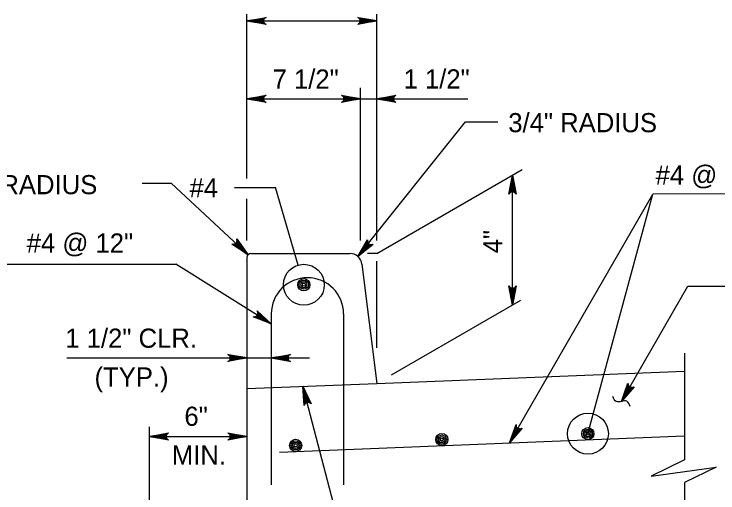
# Model space of a CAD drawing. Extents: x 2084213 to 2099800, y 976677 to 981262.
# Drawn here: x 2084499.7 to 2084861, y 980102.2 to 980348 of the extents above; entities that cross this region are included whole.
import ezdxf

# ---------------------------------------------------------------- set-up
doc = ezdxf.new("R2010")
doc.units = 0
doc.layers.add('1', color=7, linetype='Continuous')

msp = doc.modelspace()

# ---------------------------------------------------------------- linework, layer by layer
at = {"layer": '1'}
for p, q in [((2084619.23, 980263.61), (2084619.23, 980348)), ((2084685.9, 980231.81), (2084685.9, 980348)), ((2084619.23, 980344.49), (2084685.9, 980344.49)), ((2084677.57, 980231.81), (2084677.57, 980310.17)), ((2084619.23, 980304.49), (2084732.61, 980304.49)), ((2084676.18, 980223.52), (2084731.38, 980292.64)), ((2084731.38, 980292.64), (2084748.01, 980292.64)), ((2084685.9, 980225.09), (2084760.44, 980268.13)), ((2084755.54, 980198.63), (2084755.54, 980265.3)), ((2084565.45, 980261.28), (2084580.38, 980261.28)), ((2084619.84, 980224.48), (2084580.38, 980261.28)), ((2084612.8, 980258.99), (2084633.86, 980258.99)), ((2084645.5, 980219.13), (2084633.86, 980258.99)), ((2084619.23, 980231.81), (2084619.23, 980253.12)), ((2084754.04, 980127.85), (2084827.52, 980255.57)), ((2084794.23, 980132.58), (2084827.52, 980255.57)), ((2084899.18, 980255.69), (2084827.52, 980255.57)), ((2084621.31, 980225.09), (2084672.05, 980225.09)), ((2084685.9, 980225.09), (2084681.03, 980225.09)), ((2084619.23, 980223.01), (2084619.23, 980089.1)), ((2084685.9, 980176.64), (2084685.9, 980221.15)), ((2084493.44, 980219.64), (2084582.81, 980219.64)), ((2084631.73, 980188.93), (2084582.81, 980219.64)), ((2084678.25, 980219.61), (2084685.9, 980158.42)), ((2084648.44, 980209.05), (2084648.44, 980209.05)), ((2084811.49, 980149.12), (2084845.5, 980208.25)), ((2084845.5, 980208.25), (2084884.47, 980208.25)), ((2084693.43, 980162.77), (2084759.85, 980201.12)), ((2084631.73, 980194.09), (2084631.73, 980106.27)), ((2084668.84, 980194.08), (2084668.84, 980106.26)), ((2084843.77, 980173.96), (2084843.77, 980119.13)), ((2084526.78, 980171.44), (2084651.34, 980171.44)), ((2084685.9, 980158.42), (2084843.77, 980164.73)), ((2084619.23, 980155.75), (2084685.9, 980158.42)), ((2084684.41, 980017.39), (2084647.99, 980156.9)), ((2084569.27, 980092.34), (2084569.27, 980136.03)), ((2084569.27, 980131.17), (2084619.23, 980131.17)), ((2084635.9, 980123.12), (2084843.77, 980131.44)), ((2084794.23, 980132.58), (2084794.23, 980132.58)), ((2084843.77, 980107.59), (2084843.77, 980038.92))]:
    msp.add_line(p, q, dxfattribs=at)
for points in [[(2084619.23, 980344.49), (2084629.01, 980346.33), (2084628.63, 980346.07), (2084628.26, 980345.81), (2084628.06, 980345.48), (2084627.87, 980345.15), (2084627.81, 980344.82), (2084627.76, 980344.49), (2084627.81, 980344.17), (2084627.87, 980343.84), (2084628.06, 980343.51), (2084628.26, 980343.18), (2084628.63, 980342.92), (2084629.01, 980342.66), (2084619.23, 980344.49), (2084628.63, 980342.92), (2084628.26, 980343.18), (2084619.23, 980344.49), (2084628.06, 980343.51), (2084627.87, 980343.84), (2084619.23, 980344.49), (2084627.81, 980344.17), (2084627.76, 980344.49), (2084619.23, 980344.49), (2084627.81, 980344.82), (2084627.87, 980345.15), (2084619.23, 980344.49), (2084628.06, 980345.48), (2084628.26, 980345.81), (2084619.23, 980344.49), (2084628.63, 980346.07)], [(2084685.9, 980344.49), (2084676.11, 980342.66), (2084676.49, 980342.92), (2084676.86, 980343.18), (2084677.06, 980343.51), (2084677.25, 980343.84), (2084677.31, 980344.17), (2084677.37, 980344.49), (2084677.31, 980344.82), (2084677.25, 980345.15), (2084677.06, 980345.48), (2084676.86, 980345.81), (2084676.49, 980346.07), (2084676.11, 980346.33), (2084685.9, 980344.49), (2084676.49, 980346.07), (2084676.86, 980345.81), (2084685.9, 980344.49), (2084677.06, 980345.48), (2084677.25, 980345.15), (2084685.9, 980344.49), (2084677.31, 980344.82), (2084677.37, 980344.49), (2084685.9, 980344.49), (2084677.31, 980344.17), (2084677.25, 980343.84), (2084685.9, 980344.49), (2084677.06, 980343.51), (2084676.86, 980343.18), (2084685.9, 980344.49), (2084676.49, 980342.92)], [(2084619.23, 980304.49), (2084629.01, 980306.33), (2084628.63, 980306.07), (2084628.26, 980305.81), (2084628.06, 980305.48), (2084627.87, 980305.15), (2084627.81, 980304.82), (2084627.76, 980304.49), (2084627.81, 980304.17), (2084627.87, 980303.84), (2084628.06, 980303.51), (2084628.26, 980303.18), (2084628.63, 980302.92), (2084629.01, 980302.66), (2084619.23, 980304.49), (2084628.63, 980302.92), (2084628.26, 980303.18), (2084619.23, 980304.49), (2084628.06, 980303.51), (2084627.87, 980303.84), (2084619.23, 980304.49), (2084627.81, 980304.17), (2084627.76, 980304.49), (2084619.23, 980304.49), (2084627.81, 980304.82), (2084627.87, 980305.15), (2084619.23, 980304.49), (2084628.06, 980305.48), (2084628.26, 980305.81), (2084619.23, 980304.49), (2084628.63, 980306.07)], [(2084677.57, 980304.49), (2084667.78, 980302.66), (2084668.16, 980302.92), (2084668.53, 980303.18), (2084668.73, 980303.51), (2084668.92, 980303.84), (2084668.98, 980304.17), (2084669.04, 980304.49), (2084668.98, 980304.82), (2084668.92, 980305.15), (2084668.73, 980305.48), (2084668.53, 980305.81), (2084668.16, 980306.07), (2084667.78, 980306.33), (2084677.57, 980304.49), (2084668.16, 980306.07), (2084668.53, 980305.81), (2084677.57, 980304.49), (2084668.73, 980305.48), (2084668.92, 980305.15), (2084677.57, 980304.49), (2084668.98, 980304.82), (2084669.04, 980304.49), (2084677.57, 980304.49), (2084668.98, 980304.17), (2084668.92, 980303.84), (2084677.57, 980304.49), (2084668.73, 980303.51), (2084668.53, 980303.18), (2084677.57, 980304.49), (2084668.16, 980302.92)], [(2084685.9, 980304.49), (2084695.68, 980306.33), (2084695.3, 980306.07), (2084694.93, 980305.81), (2084694.73, 980305.48), (2084694.54, 980305.15), (2084694.48, 980304.82), (2084694.43, 980304.49), (2084694.48, 980304.17), (2084694.54, 980303.84), (2084694.73, 980303.51), (2084694.93, 980303.18), (2084695.3, 980302.92), (2084695.68, 980302.66), (2084685.9, 980304.49), (2084695.3, 980302.92), (2084694.93, 980303.18), (2084685.9, 980304.49), (2084694.73, 980303.51), (2084694.54, 980303.84), (2084685.9, 980304.49), (2084694.48, 980304.17), (2084694.43, 980304.49), (2084685.9, 980304.49), (2084694.48, 980304.82), (2084694.54, 980305.15), (2084685.9, 980304.49), (2084694.73, 980305.48), (2084694.93, 980305.81), (2084685.9, 980304.49), (2084695.3, 980306.07)], [(2084755.54, 980265.3), (2084757.37, 980255.51), (2084757.11, 980255.89), (2084756.85, 980256.27), (2084756.52, 980256.46), (2084756.2, 980256.66), (2084755.87, 980256.71), (2084755.54, 980256.77), (2084755.21, 980256.71), (2084754.88, 980256.66), (2084754.56, 980256.46), (2084754.23, 980256.27), (2084753.97, 980255.89), (2084753.7, 980255.51), (2084755.54, 980265.3), (2084753.97, 980255.89), (2084754.23, 980256.27), (2084755.54, 980265.3), (2084754.56, 980256.46), (2084754.88, 980256.66), (2084755.54, 980265.3), (2084755.21, 980256.71), (2084755.54, 980256.77), (2084755.54, 980265.3), (2084755.87, 980256.71), (2084756.2, 980256.66), (2084755.54, 980265.3), (2084756.52, 980256.46), (2084756.85, 980256.27), (2084755.54, 980265.3), (2084757.11, 980255.89)], [(2084619.84, 980224.48), (2084611.47, 980229.88), (2084611.93, 980229.81), (2084612.38, 980229.74), (2084612.75, 980229.85), (2084613.11, 980229.95), (2084613.38, 980230.15), (2084613.65, 980230.35), (2084613.83, 980230.63), (2084614.02, 980230.9), (2084614.1, 980231.27), (2084614.19, 980231.65), (2084614.09, 980232.09), (2084614, 980232.54), (2084619.84, 980224.48), (2084614.09, 980232.09), (2084614.19, 980231.65), (2084619.84, 980224.48), (2084614.1, 980231.27), (2084614.02, 980230.9), (2084619.84, 980224.48), (2084613.83, 980230.63), (2084613.65, 980230.35), (2084619.84, 980224.48), (2084613.38, 980230.15), (2084613.11, 980229.95), (2084619.84, 980224.48), (2084612.75, 980229.85), (2084612.38, 980229.74), (2084619.84, 980224.48), (2084611.93, 980229.81)], [(2084676.18, 980223.52), (2084681.15, 980232.15), (2084681.11, 980231.7), (2084681.06, 980231.24), (2084681.18, 980230.88), (2084681.3, 980230.52), (2084681.52, 980230.26), (2084681.73, 980230.01), (2084682.02, 980229.84), (2084682.3, 980229.66), (2084682.68, 980229.6), (2084683.05, 980229.53), (2084683.5, 980229.65), (2084683.94, 980229.77), (2084676.18, 980223.52), (2084683.5, 980229.65), (2084683.05, 980229.53), (2084676.18, 980223.52), (2084682.68, 980229.6), (2084682.3, 980229.66), (2084676.18, 980223.52), (2084682.02, 980229.84), (2084681.73, 980230.01), (2084676.18, 980223.52), (2084681.52, 980230.26), (2084681.3, 980230.52), (2084676.18, 980223.52), (2084681.18, 980230.88), (2084681.06, 980231.24), (2084676.18, 980223.52), (2084681.11, 980231.7)], [(2084755.54, 980198.63), (2084753.7, 980208.41), (2084753.97, 980208.04), (2084754.23, 980207.66), (2084754.56, 980207.47), (2084754.88, 980207.27), (2084755.21, 980207.21), (2084755.54, 980207.16), (2084755.87, 980207.21), (2084756.2, 980207.27), (2084756.52, 980207.47), (2084756.85, 980207.66), (2084757.11, 980208.04), (2084757.37, 980208.41), (2084755.54, 980198.63), (2084757.11, 980208.04), (2084756.85, 980207.66), (2084755.54, 980198.63), (2084756.52, 980207.47), (2084756.2, 980207.27), (2084755.54, 980198.63), (2084755.87, 980207.21), (2084755.54, 980207.16), (2084755.54, 980198.63), (2084755.21, 980207.21), (2084754.88, 980207.27), (2084755.54, 980198.63), (2084754.56, 980207.47), (2084754.23, 980207.66), (2084755.54, 980198.63), (2084753.97, 980208.04)], [(2084631.73, 980188.93), (2084622.46, 980192.58), (2084622.92, 980192.6), (2084623.38, 980192.62), (2084623.72, 980192.8), (2084624.06, 980192.97), (2084624.28, 980193.22), (2084624.5, 980193.47), (2084624.63, 980193.78), (2084624.75, 980194.08), (2084624.76, 980194.46), (2084624.77, 980194.85), (2084624.59, 980195.27), (2084624.41, 980195.69), (2084631.73, 980188.93), (2084624.59, 980195.27), (2084624.77, 980194.85), (2084631.73, 980188.93), (2084624.76, 980194.46), (2084624.75, 980194.08), (2084631.73, 980188.93), (2084624.63, 980193.78), (2084624.5, 980193.47), (2084631.73, 980188.93), (2084624.28, 980193.22), (2084624.06, 980192.97), (2084631.73, 980188.93), (2084623.72, 980192.8), (2084623.38, 980192.62), (2084631.73, 980188.93), (2084622.92, 980192.6)], [(2084619.23, 980171.44), (2084609.44, 980169.61), (2084609.82, 980169.87), (2084610.19, 980170.13), (2084610.39, 980170.46), (2084610.58, 980170.78), (2084610.64, 980171.11), (2084610.7, 980171.44), (2084610.64, 980171.77), (2084610.58, 980172.1), (2084610.39, 980172.42), (2084610.19, 980172.75), (2084609.82, 980173.01), (2084609.44, 980173.27), (2084619.23, 980171.44), (2084609.82, 980173.01), (2084610.19, 980172.75), (2084619.23, 980171.44), (2084610.39, 980172.42), (2084610.58, 980172.1), (2084619.23, 980171.44), (2084610.64, 980171.77), (2084610.7, 980171.44), (2084619.23, 980171.44), (2084610.64, 980171.11), (2084610.58, 980170.78), (2084619.23, 980171.44), (2084610.39, 980170.46), (2084610.19, 980170.13), (2084619.23, 980171.44), (2084609.82, 980169.87)], [(2084631.73, 980171.44), (2084641.51, 980173.27), (2084641.13, 980173.01), (2084640.76, 980172.75), (2084640.56, 980172.42), (2084640.37, 980172.1), (2084640.31, 980171.77), (2084640.26, 980171.44), (2084640.31, 980171.11), (2084640.37, 980170.78), (2084640.56, 980170.46), (2084640.76, 980170.13), (2084641.13, 980169.87), (2084641.51, 980169.61), (2084631.73, 980171.44), (2084641.13, 980169.87), (2084640.76, 980170.13), (2084631.73, 980171.44), (2084640.56, 980170.46), (2084640.37, 980170.78), (2084631.73, 980171.44), (2084640.31, 980171.11), (2084640.26, 980171.44), (2084631.73, 980171.44), (2084640.31, 980171.77), (2084640.37, 980172.1), (2084631.73, 980171.44), (2084640.56, 980172.42), (2084640.76, 980172.75), (2084631.73, 980171.44), (2084641.13, 980173.01)], [(2084647.99, 980156.9), (2084652.23, 980147.9), (2084651.89, 980148.2), (2084651.54, 980148.5), (2084651.17, 980148.6), (2084650.8, 980148.71), (2084650.47, 980148.68), (2084650.14, 980148.65), (2084649.84, 980148.51), (2084649.53, 980148.37), (2084649.27, 980148.1), (2084649, 980147.83), (2084648.84, 980147.4), (2084648.68, 980146.97), (2084647.99, 980156.9), (2084648.84, 980147.4), (2084649, 980147.83), (2084647.99, 980156.9), (2084649.27, 980148.1), (2084649.53, 980148.37), (2084647.99, 980156.9), (2084649.84, 980148.51), (2084650.14, 980148.65), (2084647.99, 980156.9), (2084650.47, 980148.68), (2084650.8, 980148.71), (2084647.99, 980156.9), (2084651.17, 980148.6), (2084651.54, 980148.5), (2084647.99, 980156.9), (2084651.89, 980148.2)], [(2084811.49, 980149.12), (2084814.78, 980158.52), (2084814.82, 980158.06), (2084814.85, 980157.6), (2084815.04, 980157.27), (2084815.23, 980156.94), (2084815.49, 980156.73), (2084815.74, 980156.52), (2084816.05, 980156.4), (2084816.37, 980156.29), (2084816.75, 980156.29), (2084817.13, 980156.3), (2084817.54, 980156.49), (2084817.96, 980156.69), (2084811.49, 980149.12), (2084817.54, 980156.49), (2084817.13, 980156.3), (2084811.49, 980149.12), (2084816.75, 980156.29), (2084816.37, 980156.29), (2084811.49, 980149.12), (2084816.05, 980156.4), (2084815.74, 980156.52), (2084811.49, 980149.12), (2084815.49, 980156.73), (2084815.23, 980156.94), (2084811.49, 980149.12), (2084815.04, 980157.27), (2084814.85, 980157.6), (2084811.49, 980149.12), (2084814.82, 980158.06)], [(2084754.04, 980127.85), (2084757.33, 980137.25), (2084757.37, 980136.79), (2084757.41, 980136.33), (2084757.6, 980136), (2084757.78, 980135.67), (2084758.04, 980135.45), (2084758.3, 980135.24), (2084758.61, 980135.13), (2084758.92, 980135.01), (2084759.3, 980135.02), (2084759.68, 980135.02), (2084760.1, 980135.22), (2084760.51, 980135.42), (2084754.04, 980127.85), (2084760.1, 980135.22), (2084759.68, 980135.02), (2084754.04, 980127.85), (2084759.3, 980135.02), (2084758.92, 980135.01), (2084754.04, 980127.85), (2084758.61, 980135.13), (2084758.3, 980135.24), (2084754.04, 980127.85), (2084758.04, 980135.45), (2084757.78, 980135.67), (2084754.04, 980127.85), (2084757.6, 980136), (2084757.41, 980136.33), (2084754.04, 980127.85), (2084757.37, 980136.79)], [(2084569.27, 980131.17), (2084579.05, 980133), (2084578.67, 980132.74), (2084578.3, 980132.48), (2084578.1, 980132.15), (2084577.91, 980131.82), (2084577.85, 980131.5), (2084577.8, 980131.17), (2084577.85, 980130.84), (2084577.91, 980130.51), (2084578.1, 980130.18), (2084578.3, 980129.85), (2084578.67, 980129.59), (2084579.05, 980129.33), (2084569.27, 980131.17), (2084578.67, 980129.59), (2084578.3, 980129.85), (2084569.27, 980131.17), (2084578.1, 980130.18), (2084577.91, 980130.51), (2084569.27, 980131.17), (2084577.85, 980130.84), (2084577.8, 980131.17), (2084569.27, 980131.17), (2084577.85, 980131.5), (2084577.91, 980131.82), (2084569.27, 980131.17), (2084578.1, 980132.15), (2084578.3, 980132.48), (2084569.27, 980131.17), (2084578.67, 980132.74)], [(2084619.23, 980131.17), (2084609.44, 980129.33), (2084609.82, 980129.59), (2084610.19, 980129.85), (2084610.39, 980130.18), (2084610.58, 980130.51), (2084610.64, 980130.84), (2084610.7, 980131.17), (2084610.64, 980131.5), (2084610.58, 980131.82), (2084610.39, 980132.15), (2084610.19, 980132.48), (2084609.82, 980132.74), (2084609.44, 980133), (2084619.23, 980131.17), (2084609.82, 980132.74), (2084610.19, 980132.48), (2084619.23, 980131.17), (2084610.39, 980132.15), (2084610.58, 980131.82), (2084619.23, 980131.17), (2084610.64, 980131.5), (2084610.7, 980131.17), (2084619.23, 980131.17), (2084610.64, 980130.84), (2084610.58, 980130.51), (2084619.23, 980131.17), (2084610.39, 980130.18), (2084610.19, 980129.85), (2084619.23, 980131.17), (2084609.82, 980129.59)], [(2084843.77, 980119.13), (2084826.75, 980110.8), (2084860.05, 980115.33), (2084843.77, 980107.59)]]:
    msp.add_lwpolyline(points, dxfattribs=at)
for centre, radius in [((2084648.44, 980209.05), 10.5), ((2084648.44, 980209.05), 3.12), ((2084648.44, 980209.05), 2.34), ((2084648.44, 980209.05), 1.56), ((2084648.44, 980209.05), 0.781), ((2084794.23, 980132.58), 10.5), ((2084794.23, 980132.58), 3.12), ((2084794.23, 980132.58), 2.34), ((2084794.23, 980132.58), 1.56), ((2084794.23, 980132.58), 0.781), ((2084644.23, 980126.58), 3.12), ((2084719.23, 980129.58), 3.12), ((2084719.23, 980129.58), 2.34), ((2084719.23, 980129.58), 1.56), ((2084719.23, 980129.58), 0.781), ((2084644.23, 980126.58), 2.34), ((2084644.23, 980126.58), 1.56), ((2084644.23, 980126.58), 0.781)]:
    msp.add_circle(centre, radius, dxfattribs=at)
for centre, radius, start, end in [((2084621.31, 980223.01), 2.08, 90, 180), ((2084672.05, 980218.84), 6.25, 7.1218, 90), ((2084650.28, 980194.08), 18.56, 359.9821, 179.9821)]:
    msp.add_arc(centre, radius, start, end, dxfattribs=at)
msp.add_spline([(2084815.87, 980146.48), (2084814.17, 980149.21), (2084808.78, 980149.04), (2084807.03, 980151.61)], degree=3, dxfattribs=at)

# ---------------------------------------------------------------- texts
for s, height, p in [('7 1/2"', 9.843, (2084632.39, 980309.72)), ('1 1/2"', 9.843, (2084699.61, 980309.79)), ('3/4" RADIUS', 9.8425, (2084753.36, 980287.34)), ('#4 @ 12"', 9.843, (2084828.96, 980260.45)), ('1/4" RADIUS', 9.8425, (2084466.07, 980255.51)), ('#4', 9.843, (2084589.74, 980253.87)), ('#4 @ 12"', 9.843, (2084506.2, 980225.55)), ('1 1/2" CLR.', 9.8425, (2084526, 980176.69)), ('(TYP.)', 9.843, (2084541, 980156.77)), ('6"', 9.843, (2084587.14, 980136.61)), ('MIN.', 9.843, (2084580.71, 980116.68))]:
    msp.add_text(s, height=height, dxfattribs=at).set_placement(p)
msp.add_text('4"', height=9.843, rotation=90, dxfattribs=at).set_placement((2084750.35, 980225.17))

doc.saveas('drawing.dxf')
